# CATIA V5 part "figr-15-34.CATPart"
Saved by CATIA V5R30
Part number: Part1
Bounding box of the stored display mesh (mm): x -40.264 to 42.014, y -25.445 to 25.445, z -51 to 0.75
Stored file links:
  D:\PROJECTS\CATIA V56R 2020\Resources\Parts File\c15_catia_v5_6r2020_prt\figr-15-34.CATPart
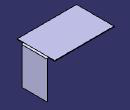
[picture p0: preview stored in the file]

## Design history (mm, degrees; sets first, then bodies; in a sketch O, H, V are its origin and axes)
SheetMetalParameters1: Thickness 0.75, BendRadius 1, KFactor 0.356492 {= log(min(100,max(20*SheetMetalParameters1.BendRadius,SheetMetalParameters1.Thickness)/SheetMetalParameters1.Thickness))/log(100)/2}, ReliefRadialLength 1, ReliefAxialLength 2, MinimumBendRadius 0
Body1 (main body)
  Sketch1 on xy-plane, origin (0, 0, 0), H (1, 0, 0), V (0, 1, 0)
    line L1 (-40.2643, 25.445) -> (40.2643, 25.445)
    line L2 (40.2643, 25.445) -> (40.2643, -25.445)
    line L3 (40.2643, -25.445) -> (-40.2643, -25.445)
    line L4 (-40.2643, -25.445) -> (-40.2643, 25.445)
    horizontal: L1 H, L3 H
    vertical: L2 V, L4 V
    symmetry: L1 L3 H, L4 L2 V
  Wall1: Thickness 0.75, Profile Sketch1
  Plane1: type Offset, RefPlane zx-plane, Offset 17
  Plane2: type Offset, RefPlane zx-plane, Offset 17, reversed
  Flange1: Angle 90, Length 50, Radius 1, KFacteur 0.356492 {= log(min(100,max(20*Flange1.Radius,SheetMetalParameters1.Thickness)/SheetMetalParameters1.Thickness))/log(100)/2}, Guide edge [face of Wall1 | face of Wall1], Limit1 Plane1, Limit2 Plane2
